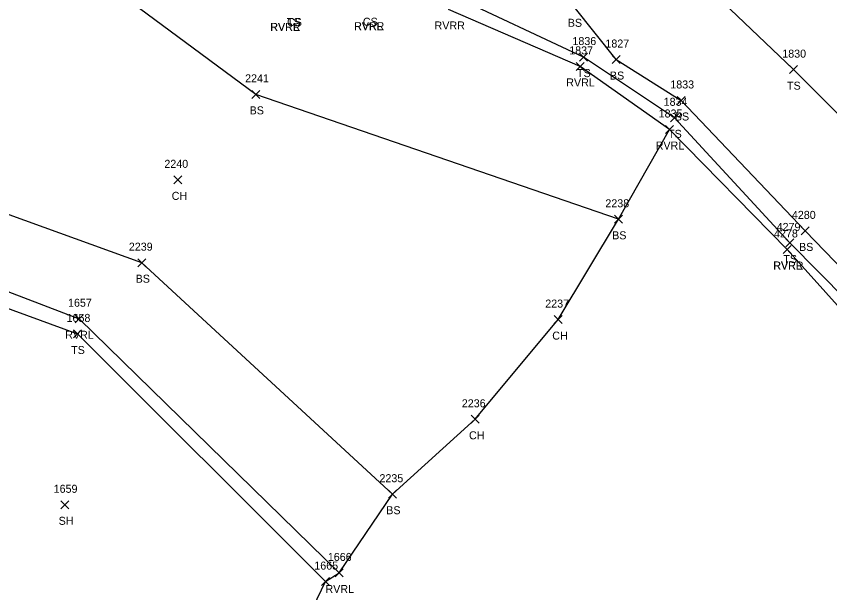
# Model space of a CAD drawing. Extents: x 1509053 to 1511576, y 400838 to 402572.
# Drawn here: x 1510281.3 to 1510484.5, y 401423.4 to 401567.3 of the extents above; entities that cross this region are included whole.
import ezdxf

# ---------------------------------------------------------------- set-up
doc = ezdxf.new("R2010")
doc.units = 0
for name, color, linetype in [('L_A', 7, 'Continuous'), ('L_I', 7, 'Continuous'), ('L_TIC', 7, 'Continuous'), ('LAWE', 7, 'Continuous'), ('LELB', 7, 'Continuous'), ('LSOGP', 7, 'Continuous')]:
    doc.layers.add(name, color=color, linetype=linetype)

msp = doc.modelspace()

# ---------------------------------------------------------------- linework, layer by layer
at = {"layer": 'L_TIC'}
for points in [[(1510421.98, 401556.12), (1510423.98, 401558.12)], [(1510423.98, 401556.12), (1510421.98, 401558.12)], [(1510430.17, 401555.5), (1510432.17, 401557.5)], [(1510432.17, 401555.5), (1510430.17, 401557.5)], [(1510421.14, 401553.8), (1510423.14, 401555.8)], [(1510423.14, 401553.8), (1510421.14, 401555.8)], [(1510474.46, 401552.99), (1510476.46, 401554.99)], [(1510476.46, 401552.99), (1510474.46, 401554.99)], [(1510340.14, 401546.81), (1510342.14, 401548.81)], [(1510342.14, 401546.81), (1510340.14, 401548.81)], [(1510446.39, 401545.28), (1510448.39, 401547.28)], [(1510448.39, 401545.28), (1510446.39, 401547.28)], [(1510444.73, 401540.95), (1510446.73, 401542.95)], [(1510446.73, 401540.95), (1510444.73, 401542.95)], [(1510443.48, 401538.03), (1510445.48, 401540.03)], [(1510445.48, 401538.03), (1510443.48, 401540.03)], [(1510320.62, 401525.46), (1510322.62, 401527.46)], [(1510322.62, 401525.46), (1510320.62, 401527.46)], [(1510430.73, 401515.62), (1510432.73, 401517.62)], [(1510432.73, 401515.62), (1510430.73, 401517.62)], [(1510477.43, 401512.71), (1510479.43, 401514.71)], [(1510479.43, 401512.71), (1510477.43, 401514.71)], [(1510473.54, 401509.7), (1510475.54, 401511.7)], [(1510475.54, 401509.7), (1510473.54, 401511.7)], [(1510472.88, 401508.07), (1510474.88, 401510.07)], [(1510474.88, 401508.07), (1510472.88, 401510.07)], [(1510472.88, 401508.07), (1510474.88, 401510.07)], [(1510474.88, 401508.07), (1510472.88, 401510.07)], [(1510311.66, 401504.77), (1510313.66, 401506.77)], [(1510313.66, 401504.77), (1510311.66, 401506.77)], [(1510295.94, 401490.77), (1510297.94, 401492.77)], [(1510297.94, 401490.77), (1510295.94, 401492.77)], [(1510415.71, 401490.56), (1510417.71, 401492.56)], [(1510417.71, 401490.56), (1510415.71, 401492.56)], [(1510295.57, 401486.98), (1510297.57, 401488.98)], [(1510297.57, 401486.98), (1510295.57, 401488.98)], [(1510394.91, 401465.66), (1510396.91, 401467.66)], [(1510396.91, 401465.66), (1510394.91, 401467.66)], [(1510374.28, 401446.95), (1510376.28, 401448.95)], [(1510376.28, 401446.95), (1510374.28, 401448.95)], [(1510292.36, 401444.31), (1510294.36, 401446.31)], [(1510294.36, 401444.31), (1510292.36, 401446.31)], [(1510360.96, 401427.29), (1510362.96, 401429.29)], [(1510362.96, 401427.29), (1510360.96, 401429.29)], [(1510357.53, 401425.13), (1510359.53, 401427.13)], [(1510359.53, 401425.13), (1510357.53, 401427.13)]]:
    msp.add_lwpolyline(points, dxfattribs=at)
at = {"layer": 'LAWE'}
for points in [[(1510422.14, 401554.79), (1510389.28, 401569.01)], [(1510444.48, 401539.03), (1510422.14, 401554.79)], [(1510473.88, 401509.07), (1510444.48, 401539.03)], [(1510025.36, 401521.25), (1510086.86, 401520.59), (1510138.35, 401521.62), (1510193.64, 401519.6), (1510247.33, 401510.69), (1510296.94, 401491.77), (1510361.96, 401428.29)], [(1510473.88, 401509.07), (1510512.58, 401466.1), (1510533.05, 401418.83)]]:
    msp.add_lwpolyline(points, dxfattribs=at)
at = {"layer": 'LELB'}
for points in [[(1510431.72, 401516.61), (1510341.14, 401547.81), (1510292.56, 401583.77), (1510226.42, 401599.28), (1510151.75, 401587.72), (1510095.68, 401580.81), (1510017.56, 401603.54), (1510015.48, 401644.92), (1509989.35, 401675.01), (1509940.27, 401707.21)], [(1510375.28, 401447.94), (1510312.66, 401505.77), (1510258.93, 401525.17), (1510195.12, 401538.28), (1510140.28, 401539.55), (1510091.11, 401540.23), (1510018.72, 401547.48), (1509966.51, 401548.78), (1509913.37, 401571.2), (1509893.6, 401622.33), (1509860.64, 401660.7)], [(1510431.17, 401556.5), (1510420.64, 401569.68), (1510411.92, 401579.72)], [(1510452.68, 401575.84), (1510475.46, 401553.98), (1510510.5, 401519.16)], [(1510445.73, 401541.95), (1510422.98, 401557.12), (1510389.58, 401572.87)], [(1510431.17, 401556.5), (1510447.39, 401546.28)], [(1510478.43, 401513.71), (1510447.39, 401546.28)], [(1510474.54, 401510.7), (1510445.73, 401541.95)], [(1510029.58, 401513.79), (1510086.69, 401518.94), (1510138.27, 401520.07), (1510192.96, 401517.24), (1510244.62, 401507.02), (1510296.57, 401487.98), (1510358.53, 401426.13)], [(1510478.43, 401513.71), (1510520.27, 401470.4), (1510555.88, 401437.67)], [(1510474.54, 401510.7), (1510517.11, 401467.72), (1510541.06, 401426.15)]]:
    msp.add_lwpolyline(points, dxfattribs=at)
at = {"layer": 'LSOGP'}
msp.add_lwpolyline([(1510344.01, 401396.04), (1510358.53, 401426.13), (1510361.96, 401428.29), (1510375.28, 401447.94), (1510395.91, 401466.66), (1510416.71, 401491.56), (1510431.72, 401516.61), (1510444.48, 401539.03), (1510473.88, 401509.07), (1510512.58, 401466.1), (1510533.05, 401418.83), (1510541.06, 401426.15), (1510555.88, 401437.67), (1510574.36, 401449.08), (1510604.93, 401471.19), (1510634.96, 401473.13), (1510676.42, 401486.89)], dxfattribs=at)

# ---------------------------------------------------------------- texts
at = {"layer": 'L_A'}
for s, p in [('TS', (1510348.89, 401564.87)), ('CS', (1510348.92, 401564.87)), ('CS', (1510367.87, 401564.94)), ('BS', (1510419.08, 401564.68)), ('RVRR', (1510344.71, 401563.64)), ('RVRL', (1510344.76, 401563.64)), ('RVRR', (1510365.66, 401563.83)), ('RVRL', (1510365.72, 401563.83)), ('RVRR', (1510385.79, 401564.01)), ('TS', (1510421.39, 401552.12)), ('BS', (1510429.61, 401551.5)), ('RVRL', (1510418.7, 401549.79)), ('TS', (1510473.87, 401548.98)), ('BS', (1510339.58, 401542.81)), ('BS', (1510445.83, 401541.28)), ('TS', (1510444.14, 401536.95)), ('RVRL', (1510441.05, 401534.03)), ('CH', (1510320.11, 401521.46)), ('BS', (1510430.17, 401511.61)), ('BS', (1510476.87, 401508.71)), ('TS', (1510472.95, 401505.7)), ('RVRR', (1510470.39, 401504.07)), ('RVRL', (1510470.45, 401504.07)), ('BS', (1510311.1, 401500.77)), ('RVRL', (1510293.5, 401486.77)), ('CH', (1510415.2, 401486.56)), ('TS', (1510294.98, 401482.98)), ('CH', (1510394.4, 401461.66)), ('BS', (1510373.72, 401442.95)), ('SH', (1510291.85, 401440.31)), ('RVRL', (1510358.53, 401423.29))]:
    msp.add_text(s, height=2, dxfattribs=at).set_placement(p)
at = {"layer": 'L_I'}
for s, p in [('1836', (1510420.24, 401560.12)), ('1827', (1510428.48, 401559.5)), ('1837', (1510419.44, 401557.79)), ('1830', (1510472.68, 401556.98)), ('2241', (1510338.45, 401550.81)), ('1833', (1510444.7, 401549.28)), ('1834', (1510443.04, 401544.95)), ('1835', (1510441.79, 401542.03)), ('2240', (1510318.27, 401529.46)), ('2238', (1510428.47, 401519.61)), ('4280', (1510475.08, 401516.71)), ('4279', (1510471.27, 401513.7)), ('4278', (1510470.62, 401512.07)), ('4278', (1510470.62, 401512.07)), ('2239', (1510309.39, 401508.77)), ('1657', (1510294.2, 401494.77)), ('2237', (1510413.45, 401494.56)), ('1658', (1510293.83, 401490.98)), ('2236', (1510392.6, 401469.66)), ('2235', (1510372.02, 401450.95)), ('1659', (1510290.61, 401448.31)), ('1666', (1510359.12, 401431.29)), ('1665', (1510355.74, 401429.13))]:
    msp.add_text(s, height=2, dxfattribs=at).set_placement(p)

doc.saveas('drawing.dxf')
